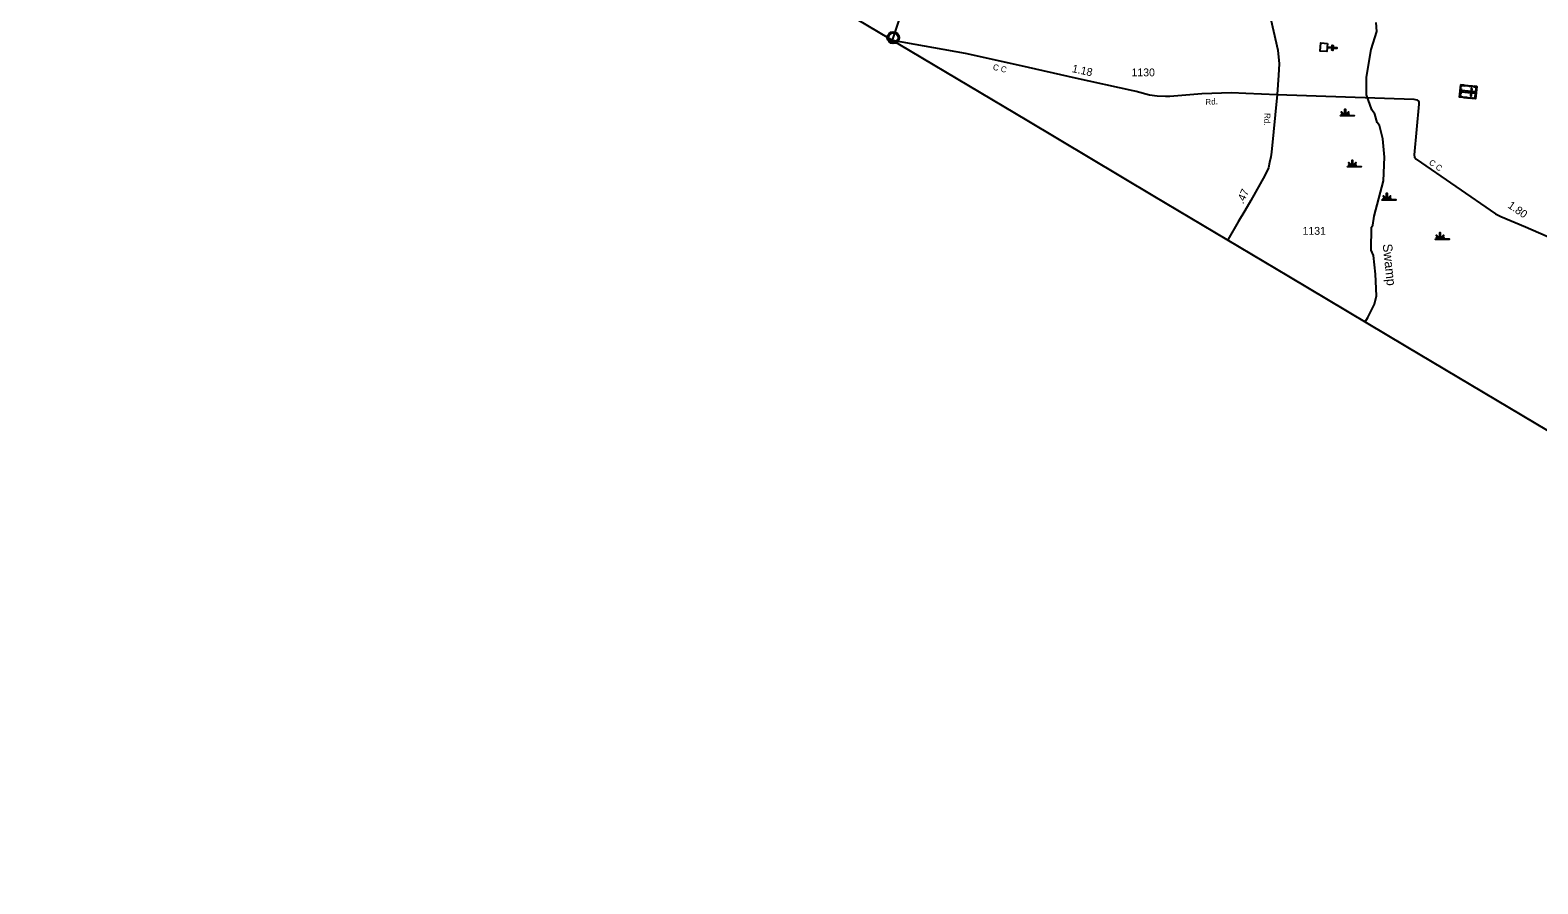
# Model space of a CAD drawing. Extents: x 2532689 to 2764727, y 536648 to 732970.
# Drawn here: x 2539489 to 2563477, y 590519 to 604102 of the extents above; entities that cross this region are included whole.
import ezdxf

# ---------------------------------------------------------------- set-up
doc = ezdxf.new("R2010")
doc.units = 0
for name, color, linetype in [('Exist Boundary Political CountyLine', 7, 'Continuous'), ('Exist Civil Demographics Community CELL', 7, 'Continuous'), ('Exist Cultural Cemetery CELL', 7, 'Continuous'), ('Exist Cultural Church CELL', 7, 'Continuous'), ('Exist Hydrographic Creek Single Shore', 7, 'Continuous'), ('Exist Hydrographic Creek Single Shore Label', 7, 'Continuous'), ('Exist Hydrographic Swamp CELL', 7, 'Continuous'), ('Exist Road Primary US Attributed', 7, 'Continuous'), ('Exist Road Secondary Mileage Hundredths English Label', 7, 'Continuous'), ('Exist Road Secondary Type 20 Attributed', 7, 'Continuous'), ('Exist Road Secondary Type 51 Attributed', 7, 'Continuous'), ('Exist Road Secondary Type 51 Label', 7, 'Continuous'), ('Exist Road Secondary Type 51 Number Label', 7, 'Continuous')]:
    doc.layers.add(name, color=color, linetype=linetype)

msp = doc.modelspace()

# ---------------------------------------------------------------- linework, layer by layer
at = {"layer": 'Exist Boundary Political CountyLine'}
msp.add_lwpolyline([(2539489, 612112), (2541484, 610924), (2543090, 609968), (2546865, 607719), (2548776, 606581), (2551142, 605172), (2553489, 603774), (2555345, 602668), (2557351, 601473), (2559512, 600187), (2561378, 599075), (2566102, 596262), (2569405, 594294), (2586179, 584303), (2593549, 579914), (2608947, 570743), (2617220, 563503), (2625601, 556169), (2628092, 553990)], dxfattribs=at)
at = {"layer": 'Exist Civil Demographics Community CELL'}
msp.add_lwpolyline([(2553144, 603995), (2553145, 604000), (2553147, 604007), (2553150, 604014), (2553152, 604020), (2553156, 604026), (2553160, 604031), (2553163, 604035), (2553168, 604040), (2553174, 604044), (2553179, 604048), (2553184, 604051), (2553189, 604053), (2553194, 604055), (2553200, 604057), (2553204, 604058), (2553209, 604059), (2553213, 604060), (2553220, 604060), (2553224, 604060), (2553230, 604060), (2553235, 604059), (2553240, 604058), (2553245, 604057), (2553250, 604055), (2553256, 604052), (2553263, 604048), (2553268, 604045), (2553273, 604041), (2553276, 604038), (2553280, 604033), (2553284, 604029), (2553287, 604024), (2553290, 604019), (2553293, 604014), (2553295, 604009), (2553297, 604004), (2553298, 603999), (2553299, 603993), (2553300, 603988), (2553300, 603982), (2553300, 603977), (2553299, 603971), (2553298, 603965), (2553296, 603959), (2553295, 603953), (2553292, 603948), (2553289, 603942), (2553286, 603937), (2553282, 603932), (2553278, 603928), (2553273, 603923), (2553268, 603919), (2553263, 603915), (2553259, 603913), (2553252, 603909), (2553245, 603907), (2553239, 603905), (2553232, 603904), (2553228, 603903), (2553223, 603903), (2553217, 603903), (2553213, 603904), (2553208, 603904), (2553202, 603906), (2553197, 603907), (2553192, 603909), (2553187, 603911), (2553183, 603913), (2553177, 603917), (2553171, 603921), (2553166, 603926), (2553162, 603931), (2553158, 603935), (2553155, 603939), (2553151, 603946), (2553150, 603949), (2553148, 603954), (2553145, 603962), (2553144, 603969), (2553143, 603974), (2553143, 603980), (2553143, 603985), (2553143, 603991)], close=True, dxfattribs=at)
for centre, radius in [((2553221, 603982), 94.3), ((2553221, 603983), 76.7)]:
    msp.add_circle(centre, radius, dxfattribs=at)
at = {"layer": 'Exist Cultural Cemetery CELL'}
for points in [[(2562505, 603207), (2562485, 603009), (2562232, 603034), (2562251, 603232)], [(2562235, 603067), (2562247, 603065), (2562244, 603044), (2562285, 603040), (2562284, 603029), (2562232, 603034)], [(2562257, 603173), (2562249, 603089), (2562238, 603090), (2562246, 603175)], [(2562248, 603199), (2562259, 603198), (2562262, 603220), (2562302, 603216), (2562303, 603227), (2562251, 603232)], [(2562465, 603101), (2562467, 603120), (2562265, 603140), (2562263, 603121)], [(2562321, 603225), (2562364, 603221), (2562363, 603209), (2562320, 603214)], [(2562388, 603218), (2562431, 603214), (2562430, 603203), (2562387, 603207)], [(2562433, 603173), (2562414, 603175), (2562403, 603058), (2562422, 603056)], [(2562442, 603013), (2562443, 603024), (2562475, 603021), (2562479, 603062), (2562490, 603061), (2562485, 603009)], [(2562462, 603211), (2562460, 603200), (2562492, 603197), (2562489, 603157), (2562500, 603155), (2562505, 603207)], [(2562497, 603133), (2562492, 603082), (2562481, 603083), (2562486, 603135)], [(2562305, 603038), (2562348, 603034), (2562347, 603022), (2562304, 603027)], [(2562371, 603032), (2562414, 603027), (2562413, 603016), (2562369, 603020)]]:
    msp.add_lwpolyline(points, close=True, dxfattribs=at)
at = {"layer": 'Exist Cultural Church CELL'}
msp.add_lwpolyline([(2560130, 603891), (2560127, 603834), (2560203, 603829), (2560205, 603861), (2560221, 603860), (2560219, 603828), (2560279, 603825), (2560278, 603809), (2560218, 603812), (2560216, 603780), (2560200, 603781), (2560202, 603813), (2560126, 603818), (2560122, 603761), (2560016, 603767), (2560024, 603898)], close=True, dxfattribs=at)
at = {"layer": 'Exist Hydrographic Creek Single Shore'}
msp.add_lwpolyline([(2560730, 599461), (2560772, 599532), (2560877, 599743), (2560908, 599876), (2560892, 600220), (2560862, 600517), (2560827, 600601), (2560828, 600965), (2560852, 600999), (2560874, 601141), (2561022, 601705), (2561039, 602080), (2561009, 602371), (2560955, 602586), (2560920, 602634), (2560884, 602767), (2560833, 602834), (2560753, 603074), (2560748, 603356), (2560823, 603792), (2560917, 604078), (2560906, 604225)], dxfattribs=at)
at = {"layer": 'Exist Hydrographic Swamp CELL'}
for points in [[(2560336, 602743), (2560388, 602743), (2560390, 602747), (2560352, 602762), (2560355, 602767), (2560393, 602751), (2560394, 602754), (2560350, 602798), (2560355, 602804), (2560400, 602758), (2560407, 602760), (2560407, 602844), (2560414, 602844), (2560414, 602760), (2560420, 602758), (2560465, 602804), (2560471, 602798), (2560426, 602754), (2560428, 602750), (2560469, 602769), (2560471, 602764), (2560430, 602746), (2560432, 602743), (2560553, 602743), (2560553, 602736), (2560336, 602736)], [(2560449, 601933), (2560502, 601933), (2560504, 601937), (2560466, 601952), (2560468, 601957), (2560506, 601941), (2560508, 601944), (2560463, 601989), (2560468, 601994), (2560514, 601948), (2560520, 601951), (2560520, 602034), (2560527, 602034), (2560527, 601951), (2560534, 601948), (2560579, 601994), (2560584, 601989), (2560540, 601944), (2560542, 601940), (2560583, 601959), (2560585, 601954), (2560544, 601936), (2560546, 601933), (2560667, 601933), (2560667, 601926), (2560449, 601926)], [(2561000, 601406), (2561052, 601406), (2561054, 601410), (2561016, 601425), (2561019, 601430), (2561057, 601414), (2561058, 601417), (2561014, 601462), (2561019, 601467), (2561064, 601421), (2561071, 601424), (2561071, 601507), (2561078, 601507), (2561078, 601424), (2561084, 601421), (2561130, 601467), (2561135, 601462), (2561090, 601417), (2561092, 601414), (2561133, 601432), (2561136, 601427), (2561095, 601409), (2561096, 601406), (2561217, 601406), (2561217, 601399), (2561000, 601399)], [(2561846, 600780), (2561899, 600780), (2561901, 600784), (2561863, 600799), (2561866, 600804), (2561903, 600788), (2561905, 600791), (2561861, 600836), (2561866, 600841), (2561911, 600795), (2561917, 600798), (2561917, 600881), (2561925, 600881), (2561925, 600798), (2561931, 600795), (2561976, 600841), (2561981, 600836), (2561937, 600791), (2561939, 600788), (2561980, 600806), (2561982, 600801), (2561941, 600783), (2561943, 600780), (2562064, 600780), (2562064, 600773), (2561846, 600773)]]:
    msp.add_lwpolyline(points, close=True, dxfattribs=at)
at = {"layer": 'Exist Road Primary US Attributed'}
msp.add_lwpolyline([(2553208, 603941), (2553370, 604418), (2553458, 604656), (2553552, 604935), (2553816, 605700), (2553995, 606216), (2554221, 606881), (2554487, 607652), (2554923, 608925), (2554966, 609023), (2555104, 609444), (2555329, 610097), (2555622, 610940), (2555823, 611508), (2556335, 613022), (2556447, 613331), (2556464, 613382), (2557023, 615034), (2557168, 615414), (2557290, 615784), (2557415, 616128)], dxfattribs=at)
at = {"layer": 'Exist Road Secondary Type 20 Attributed'}
msp.add_lwpolyline([(2559330, 603080), (2561504, 603003), (2561554, 602992), (2561583, 602966), (2561585, 602924), (2561507, 602119), (2561512, 602083), (2561539, 602051), (2562802, 601178), (2562890, 601137), (2563278, 600975), (2564922, 600255), (2565210, 600149), (2567195, 599289)], dxfattribs=at)
at = {"layer": 'Exist Road Secondary Type 51 Attributed'}
for points in [[(2558960, 605451), (2559065, 604997), (2559339, 603782), (2559361, 603566), (2559351, 603384), (2559330, 603080)], [(2553208, 603941), (2554366, 603734), (2555252, 603539), (2556114, 603345), (2557032, 603139), (2557084, 603129), (2557299, 603075), (2557421, 603056), (2557550, 603049), (2557623, 603052), (2558131, 603094), (2558603, 603109), (2558830, 603100), (2559330, 603080)], [(2559330, 603080), (2559238, 602161), (2559229, 602084), (2559208, 601996), (2559189, 601910), (2559132, 601788), (2558910, 601392), (2558814, 601227), (2558711, 601054), (2558542, 600764)]]:
    msp.add_lwpolyline(points, dxfattribs=at)

# ---------------------------------------------------------------- texts
at = {"layer": 'Exist Hydrographic Creek Single Shore Label'}
msp.add_text('Swamp', height=150, rotation=275.7859, dxfattribs=at).set_placement((2561008, 600695))
at = {"layer": 'Exist Road Secondary Mileage Hundredths English Label'}
for s, rotation, p in [('1.18', 347.8449, (2556058, 603435)), ('.47', 65.7217, (2558790, 601328)), ('1.80', 325.4878, (2562987, 601287))]:
    msp.add_text(s, height=125, rotation=rotation, dxfattribs=at).set_placement(p)
at = {"layer": 'Exist Road Secondary Type 51 Label'}
for s, rotation, p in [('C C', 347.0977, (2554800, 603472)), ('Rd.', 3.3668, (2558190, 602911)), ('Rd.', 267.9612, (2559127, 602784)), ('C C', 325.3355, (2561735, 601975))]:
    msp.add_text(s, height=95, rotation=rotation, dxfattribs=at).set_placement(p)
at = {"layer": 'Exist Road Secondary Type 51 Number Label'}
for s, p in [('1130', (2557012, 603367)), ('1131', (2559733, 600846))]:
    msp.add_text(s, height=125, dxfattribs=at).set_placement(p)

doc.saveas('drawing.dxf')
